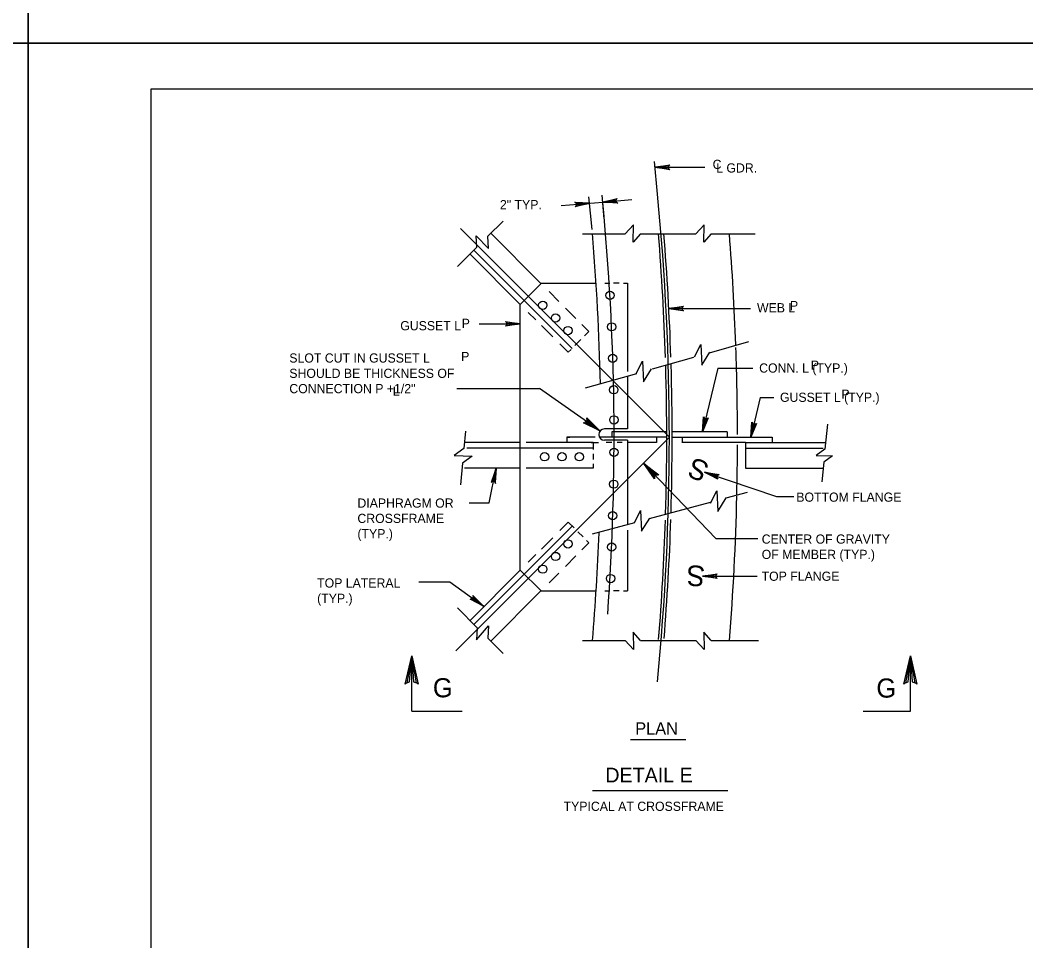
# Model space of a CAD drawing. Extents: x 30 to 2621, y -33 to 1155.
# Drawn here: x 1709.8 to 2038.5, y 267.8 to 568.5 of the extents above; entities that cross this region are included whole.
import ezdxf

# ---------------------------------------------------------------- set-up
doc = ezdxf.new("R2010")
doc.units = 0
doc.layers.add('1', color=7, linetype='Continuous')
doc.layers.add('PLT-BNDY', color=7, linetype='Continuous')

msp = doc.modelspace()

# ---------------------------------------------------------------- linework, layer by layer
at = {"layer": '1'}
for p, q in [((1752.5, 546), (1752.5, -18)), ((2538.5, 546), (1752.5, 546)), ((1918.1, 511.63), (1917.1, 522.37)), ((1917.28, 520.42), (1933.53, 520.42)), ((1896.71, 500.09), (1895.7, 510.83)), ((1900.71, 503.59), (1899.99, 511.28)), ((1900.2, 509.07), (1909.67, 509.88)), ((1886.62, 507.91), (1900.2, 509.07)), ((1862.62, 497.88), (1867.62, 502.88)), ((1853.74, 500.49), (1921.97, 432.26)), ((1863.6, 498.86), (1879.87, 482.59)), ((1893.63, 498.69), (1907.58, 498.69)), ((1912.56, 498.69), (1930.68, 498.69)), ((1935.66, 498.69), (1950.03, 498.69)), ((1852.76, 488.03), (1859.1, 494.36)), ((1858.13, 493.4), (1890.24, 461.29)), ((1856.84, 492.1), (1873.28, 475.66)), ((1873.28, 475.66), (1880.04, 482.42)), ((1879.87, 482.59), (1898.02, 482.59)), ((1882.65, 479.81), (1885.85, 476.61)), ((1900.92, 482.59), (1902.53, 482.59)), ((1905.56, 482.59), (1903.76, 482.59)), ((1906.98, 482.59), (1908.26, 482.59)), ((1908.26, 482.59), (1908.26, 453.74)), ((1873.28, 388.86), (1873.28, 475.66)), ((1888.01, 474.45), (1891.4, 471.05)), ((1921.8, 474.28), (1948.52, 474.28)), ((1875.89, 473.05), (1878.32, 470.61)), ((1859.82, 469.32), (1873.28, 469.32)), ((1880.16, 468.78), (1883.86, 465.08)), ((1893.37, 469.09), (1895.71, 466.75)), ((1894.29, 465.34), (1895.71, 466.75)), ((1891.13, 462.17), (1893.09, 464.13)), ((1935.09, 459.85), (1947.98, 463.51)), ((1886.2, 462.74), (1888.95, 459.99)), ((1888.95, 459.99), (1889.88, 460.92)), ((1916.47, 454.56), (1929.97, 458.4)), ((1937.77, 454.84), (1932.76, 434.03)), ((1937.77, 454.84), (1949.22, 454.84)), ((1894.54, 448.34), (1911.3, 453.1)), ((1908.26, 452.23), (1908.26, 434.97)), ((1852.53, 448.19), (1879.56, 448.19)), ((1899.3, 434.36), (1879.56, 448.19)), ((1951.68, 445.24), (1948.55, 432.26)), ((1951.68, 445.24), (1956.07, 445.24)), ((1855.38, 434.22), (1854.84, 428.55)), ((1908.26, 434.97), (1900.73, 434.97)), ((1903.16, 434.03), (1903.16, 432.26)), ((1921.12, 434.03), (1903.16, 434.03)), ((1940.85, 434.03), (1922.89, 434.03)), ((1940.85, 434.03), (1940.85, 432.26)), ((1973.61, 436.56), (1972.83, 428.37)), ((1852.18, 362.47), (1921.97, 432.26)), ((1888.46, 432.26), (1888.46, 430.49)), ((1888.46, 432.26), (1889.44, 432.26)), ((1897.78, 432.26), (1888.46, 432.26)), ((1921.13, 432.26), (1899.1, 432.26)), ((1908.26, 431.29), (1900.73, 431.29)), ((1908.26, 431.29), (1908.26, 403.73)), ((1917.77, 432.24), (1917.77, 430.49)), ((1922.89, 432.26), (1955.55, 432.26)), ((1926.17, 432.24), (1926.17, 430.47)), ((1955.55, 432.26), (1955.55, 430.49)), ((1873.28, 430.49), (1855.07, 430.49)), ((1897.12, 428.66), (1855.77, 428.66)), ((1897.12, 430.49), (1875.2, 430.49)), ((1896.4, 430.49), (1898.82, 430.49)), ((1897.12, 430.49), (1897.12, 428.25)), ((1903.18, 430.49), (1901.35, 430.49)), ((1906.58, 430.49), (1904.92, 430.49)), ((1917.77, 430.49), (1908.24, 430.49)), ((1946.89, 430.49), (1926.17, 430.49)), ((1946.89, 430.49), (1973.03, 430.49)), ((1946.89, 430.49), (1946.89, 422.12)), ((1946.89, 428.66), (1972.2, 428.66)), ((1897.12, 426.84), (1897.12, 425.03)), ((1972.42, 424.07), (1971.82, 417.74)), ((1854.38, 423.77), (1853.71, 416.74)), ((1873.28, 422.12), (1855.07, 422.12)), ((1863.13, 410.82), (1865.43, 422.1)), ((1897.12, 422.12), (1875.2, 422.12)), ((1897.12, 423.56), (1897.12, 422.12)), ((1913.67, 423.65), (1937.16, 399.14)), ((1933.43, 420.88), (1957.03, 412.86)), ((1946.89, 422.12), (1972.2, 422.12)), ((1940.57, 412.43), (1947.46, 414.28)), ((1856.54, 410.82), (1863.13, 410.82)), ((1915.46, 405.67), (1935.41, 411.04)), ((1957.03, 412.86), (1962.61, 412.86)), ((1886.2, 401.78), (1888.95, 404.53)), ((1888.95, 404.53), (1890.82, 402.66)), ((1896.86, 400.67), (1910.67, 404.38)), ((1858.13, 371.13), (1890.24, 403.23)), ((1892.11, 401.37), (1893.78, 399.7)), ((1908.26, 401.89), (1908.26, 382.1)), ((1880.16, 395.75), (1883.86, 399.44)), ((1893.37, 395.44), (1895.71, 397.77)), ((1894.9, 398.57), (1895.71, 397.77)), ((1937.16, 399.14), (1950.85, 399.14)), ((1875.89, 391.47), (1878.32, 393.91)), ((1888.01, 390.07), (1891.4, 393.47)), ((1856.84, 372.42), (1873.28, 388.86)), ((1873.28, 388.86), (1880.04, 382.1)), ((1882.65, 384.71), (1885.85, 387.91)), ((1840.15, 385.04), (1850.25, 385.04)), ((1850.25, 385.04), (1861.26, 377.13)), ((1932.78, 386.92), (1950.62, 386.92)), ((1863.6, 365.66), (1879.87, 381.93)), ((1880.04, 382.1), (1898.06, 382.1)), ((1900.92, 382.1), (1902.53, 382.1)), ((1905.56, 382.1), (1903.76, 382.1)), ((1906.98, 382.1), (1908.26, 382.1)), ((1852.76, 376.5), (1859.23, 370.03)), ((1862.62, 366.64), (1867.62, 361.64)), ((1893.63, 365.83), (1907.58, 365.83)), ((1912.56, 365.83), (1930.68, 365.83)), ((1935.66, 365.83), (1951.15, 365.83)), ((1837.79, 342.79), (1837.79, 360.87)), ((2000.72, 342.79), (2000.72, 360.87)), ((1837.79, 342.79), (1854.27, 342.79)), ((1985.27, 342.79), (2000.72, 342.79)), ((1909.26, 333.58), (1927.35, 333.58)), ((1896.9, 316.84), (1941.06, 316.84))]:
    msp.add_line(p, q, dxfattribs=at)
for points in [[(1921.9, 519.85), (1921.72, 520.18), (1917.28, 520.42), (1921.9, 519.85), (1922.13, 519.64), (1917.28, 520.42), (1921.72, 520.64), (1921.88, 520.97), (1917.28, 520.42), (1922.13, 521.2), (1921.88, 520.97)], [(1904.85, 508.88), (1904.65, 509.2), (1900.2, 509.07), (1904.85, 508.88), (1905.1, 508.7), (1900.2, 509.07), (1904.6, 509.67), (1904.74, 510.01), (1900.2, 509.07), (1904.97, 510.25), (1904.74, 510.01)], [(1891.3, 508.89), (1891.5, 508.57), (1895.94, 508.7), (1891.3, 508.89), (1891.05, 509.07), (1895.94, 508.7), (1891.54, 508.11), (1891.41, 507.76), (1895.94, 508.7), (1891.18, 507.52), (1891.41, 507.76)], [(1912.56, 498.69), (1910.14, 495.94), (1910.22, 501.65), (1907.58, 498.69)], [(1935.66, 498.69), (1933.24, 495.94), (1933.32, 501.65), (1930.68, 498.69)], [(1859.1, 494.36), (1858.87, 498.01), (1862.86, 493.92), (1862.62, 497.88)], [(1926.42, 473.7), (1926.24, 474.04), (1921.8, 474.28), (1926.42, 473.7), (1926.65, 473.5), (1921.8, 474.28), (1926.24, 474.5), (1926.4, 474.83), (1921.8, 474.28), (1926.65, 475.05), (1926.4, 474.83)], [(1868.67, 469.89), (1868.84, 469.56), (1873.28, 469.32), (1868.67, 469.89), (1868.43, 470.1), (1873.28, 469.32), (1868.84, 469.1), (1868.68, 468.77), (1873.28, 469.32), (1868.43, 468.54), (1868.68, 468.77)], [(1930.18, 458.47), (1932.23, 462.55), (1932.54, 455.8), (1935.21, 460.04)], [(1911.15, 453.04), (1913.19, 457.12), (1913.51, 450.37), (1916.18, 454.61)], [(1895.06, 438.2), (1895, 437.74), (1899.3, 434.36), (1895.06, 438.2), (1894.97, 438.57), (1899.3, 434.36), (1894.68, 437.27), (1894.28, 437.05), (1899.3, 434.36), (1893.87, 437.01), (1894.28, 437.05)], [(1934.4, 438.38), (1934.04, 438.29), (1932.76, 434.03), (1934.4, 438.38), (1934.65, 438.56), (1932.76, 434.03), (1933.58, 438.4), (1933.3, 438.63), (1932.76, 434.03), (1933.14, 438.93), (1933.3, 438.63)], [(1950.2, 436.61), (1949.83, 436.52), (1948.55, 432.26), (1950.2, 436.61), (1950.45, 436.79), (1948.55, 432.26), (1949.38, 436.63), (1949.1, 436.86), (1948.55, 432.26), (1948.94, 437.16), (1949.1, 436.86)], [(1854.84, 428.55), (1851.68, 426.25), (1857.58, 426.11), (1854.38, 423.77)], [(1972.83, 428.37), (1969.98, 426.3), (1975.3, 426.18), (1972.42, 424.07)], [(1865.07, 417.46), (1864.78, 417.7), (1865.43, 422.1), (1865.07, 417.46), (1865.22, 417.19), (1865.43, 422.1), (1864.33, 417.8), (1863.97, 417.7), (1865.43, 422.1), (1863.7, 417.5), (1863.97, 417.7)], [(1917.09, 419.06), (1917.24, 419.5), (1913.67, 423.65), (1917.09, 419.06), (1917.11, 418.68), (1913.67, 423.65), (1917.65, 419.89), (1918.08, 420.03), (1913.67, 423.65), (1918.49, 420), (1918.08, 420.03)], [(1937.62, 418.85), (1937.56, 419.22), (1933.43, 420.88), (1937.62, 418.85), (1937.77, 418.58), (1933.43, 420.88), (1937.71, 419.66), (1937.97, 419.92), (1933.43, 420.88), (1938.27, 420.05), (1937.97, 419.92)], [(1935.44, 410.69), (1937.48, 414.77), (1937.79, 408.02), (1940.59, 412.46)], [(1910.54, 404.26), (1912.58, 408.35), (1912.9, 401.59), (1915.56, 405.83)], [(1937.39, 386.34), (1937.22, 386.67), (1932.78, 386.92), (1937.39, 386.34), (1937.63, 386.13), (1932.78, 386.92), (1937.22, 387.13), (1937.38, 387.47), (1932.78, 386.92), (1937.63, 387.69), (1937.38, 387.47)], [(1857.86, 380.29), (1857.8, 379.92), (1861.26, 377.13), (1857.86, 380.29), (1857.78, 380.59), (1861.26, 377.13), (1857.53, 379.54), (1857.21, 379.36), (1861.26, 377.13), (1856.88, 379.33), (1857.21, 379.36)], [(1859.23, 370.03), (1858.98, 366.13), (1862.86, 370.6), (1862.62, 366.64)], [(1912.56, 365.83), (1910.14, 368.58), (1910.22, 362.87), (1907.58, 365.83)], [(1935.66, 365.83), (1933.24, 368.58), (1933.32, 362.87), (1930.68, 365.83)], [(1836.19, 352.02), (1837.11, 352.35), (1837.79, 360.87), (1836.19, 352.02), (1835.63, 351.56), (1837.79, 360.87), (1838.4, 352.35), (1839.31, 352.04), (1837.79, 360.87), (1839.92, 351.56), (1839.31, 352.04)], [(1999.12, 352.02), (2000.04, 352.35), (2000.72, 360.87), (1999.12, 352.02), (1998.56, 351.56), (2000.72, 360.87), (2001.32, 352.35), (2002.24, 352.04), (2000.72, 360.87), (2002.85, 351.56), (2002.24, 352.04)]]:
    msp.add_lwpolyline(points, dxfattribs=at)
for centre in [(1902.59, 478.59), (1880.61, 475.36), (1884.79, 471.21), (1888.87, 467.1), (1903.11, 468.31), (1903.46, 458.04), (1903.81, 447.76), (1903.85, 437.92), (1881.2, 425.88), (1886.88, 425.88), (1892.55, 425.88), (1903.9, 427.34), (1903.81, 416.93), (1903.46, 406.65), (1888.87, 397.42), (1903.11, 396.38), (1884.79, 393.31), (1880.61, 389.16), (1902.76, 386.1)]:
    msp.add_circle(centre, 1.35, dxfattribs=at)
for centre, radius, start, end in [((1102.08, 432.1), 801.83, 355.88126, 5.56644), ((1102.08, 432.1), 819.89, 354.42094, 5.56644), ((1102.08, 432.1), 797.54, 1.26565, 4.79617), ((1102.08, 432.1), 819.05, 1.8329, 4.66297), ((1102.08, 432.1), 820.81, 1.83924, 4.65295), ((1102.08, 432.1), 842.15, 2.06404, 4.53477), ((1102.08, 432.1), 842.15, 0.07031, 2.00517), ((1102.08, 432.1), 819.05, 358.25144, 1.64857), ((1102.08, 432.1), 820.81, 358.28063, 1.6666), ((1900.73, 433.13), 1.84, 90, 270), ((1102.08, 432.1), 842.15, 358.74061, 359.84445), ((1102.08, 432.1), 842.15, 355.48674, 358.70461), ((1102.08, 432.1), 819.05, 355.38412, 358.1171), ((1102.08, 432.1), 820.81, 355.41582, 358.13448), ((1102.08, 432.1), 797.54, 355.23373, 357.77089)]:
    msp.add_arc(centre, radius, start, end, dxfattribs=at)
at = {"layer": 'PLT-BNDY'}
for points in [[(871.5, 1155), (1712.5, 1155), (1712.5, 561), (871.5, 561)], [(1712.5, 1155), (2553.5, 1155), (2553.5, 561), (1712.5, 561)], [(871.5, 561), (1712.5, 561), (1712.5, -33), (871.5, -33)], [(1712.5, 561), (2553.5, 561), (2553.5, -33), (1712.5, -33)]]:
    msp.add_lwpolyline(points, close=True, dxfattribs=at)

# ---------------------------------------------------------------- texts
at = {"layer": '1'}
for s, height, p in [('C', 3, (1936.11, 519.89)), ('L GDR.', 3, (1937.28, 518.72)), ('2" TYP.', 3, (1866.62, 506.74)), ('P', 3, (1961.39, 473.75)), ('WEB L', 3, (1950.62, 473.05)), ('GUSSET L', 3, (1834.05, 467.19)), ('P', 3, (1854.12, 467.96)), ('P', 3, (1853.94, 457.14)), ('SLOT CUT IN GUSSET L', 3, (1797.8, 456.64)), ('P', 3, (1968.18, 454.31)), ('SHOULD BE THICKNESS OF', 3, (1797.8, 451.64)), ('CONN. L (TYP.)', 3, (1951.32, 453.37)), ('CONNECTION P +1/2"', 3, (1797.8, 446.64)), ('L', 3, (1831.61, 445.79)), ('GUSSET L (TYP.)', 3, (1958.12, 443.81)), ('P', 3, (1978.19, 444.82)), ('BOTTOM FLANGE', 3, (1963.46, 411.19)), ('DIAPHRAGM OR', 3, (1820.05, 409.25)), ('CROSSFRAME', 3, (1820.05, 404.25)), ('(TYP.)', 3, (1820.05, 399.25)), ('CENTER OF GRAVITY', 3, (1952.15, 397.49)), ('OF MEMBER (TYP.)', 3, (1952.15, 392.49)), ('TOP FLANGE', 3, (1952.12, 385.36)), ('TOP LATERAL', 3, (1806.89, 383.15)), ('(TYP.)', 3, (1806.89, 378.15)), ('G', 6.24, (1844.7, 347.31)), ('G', 6.24, (1989.61, 347.21)), ('PLAN', 4, (1910.81, 335.14)), ('DETAIL E', 4.8, (1901.06, 319.51)), ('TYPICAL AT CROSSFRAME', 3, (1887.42, 310.21))]:
    msp.add_text(s, height=height, dxfattribs=at).set_placement(p)
for rotation, p in [(157.4543, (1935.47, 423.6)), (176.2424, (1933.83, 390.14))]:
    msp.add_text('S', height=6.72, rotation=rotation, dxfattribs=at).set_placement(p)

doc.saveas('drawing.dxf')
